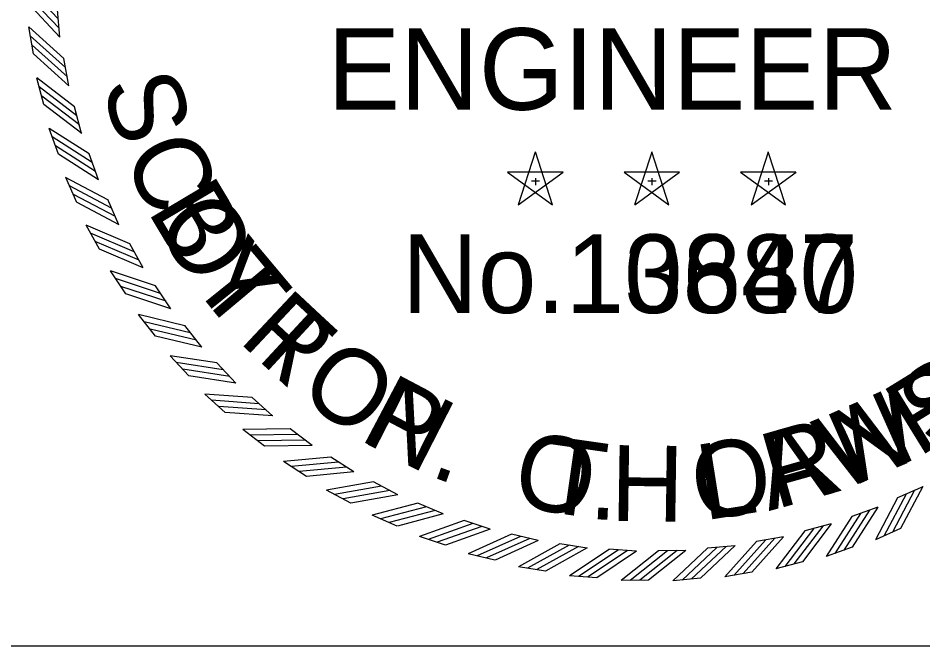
# Model space of a CAD drawing. Extents: x 0 to 1228740, y 0 to 152440.
# Drawn here: x 30.801 to 32.593, y 17.405 to 18.649 of the extents above; entities that cross this region are included whole.
import ezdxf

# ---------------------------------------------------------------- set-up
doc = ezdxf.new("R2010")
doc.units = 0
for name, color, linetype in [('R_No Plot', 7, 'Continuous'), ('STAMP_BOL', 7, 'Continuous'), ('STAMP_PP', 7, 'Continuous')]:
    doc.layers.add(name, color=color, linetype=linetype)

msp = doc.modelspace()

# ---------------------------------------------------------------- linework, layer by layer
at = {"layer": 'R_No Plot'}
msp.add_lwpolyline([(30.6665, 20.1432), (30.6665, 17.4052), (33.4231, 17.4052)], dxfattribs=at)
at = {"layer": 'STAMP_BOL'}
for p, q in [((30.8837, 18.6117), (30.8787, 18.666)), ((30.8314, 18.5785), (30.822, 18.6321)), ((30.9013, 18.5154), (30.8918, 18.5691)), ((30.8519, 18.478), (30.8381, 18.5306)), ((30.9268, 18.4209), (30.9129, 18.4737)), ((30.8807, 18.3796), (30.8626, 18.4309)), ((30.96, 18.3289), (30.9419, 18.3803)), ((31.8255, 18.384), (31.7915, 18.2795)), ((31.8594, 18.2796), (31.8256, 18.3841)), ((32.0563, 18.384), (32.0222, 18.2795)), ((32.0902, 18.2796), (32.0564, 18.3841)), ((32.2871, 18.384), (32.253, 18.2795)), ((32.321, 18.2796), (32.2871, 18.3841)), ((31.8804, 18.3441), (31.7705, 18.3442)), ((31.7706, 18.3441), (31.8594, 18.2795)), ((31.7916, 18.2796), (31.8805, 18.3441)), ((32.1112, 18.3441), (32.0013, 18.3442)), ((32.0014, 18.3441), (32.0902, 18.2795)), ((32.0224, 18.2796), (32.1113, 18.3441)), ((32.3419, 18.3441), (32.2321, 18.3442)), ((32.2322, 18.3441), (32.321, 18.2795)), ((32.2532, 18.2796), (32.3421, 18.3441)), ((30.9175, 18.2838), (30.8952, 18.3335)), ((31.8177, 18.3266), (31.834, 18.3266)), ((31.8256, 18.3324), (31.8256, 18.3186)), ((32.0485, 18.3266), (32.0648, 18.3266)), ((32.0564, 18.3324), (32.0564, 18.3186)), ((32.2793, 18.3266), (32.2956, 18.3266)), ((32.2872, 18.3324), (32.2872, 18.3186)), ((31.0007, 18.2399), (30.9784, 18.2896)), ((30.9621, 18.1915), (30.9357, 18.2391)), ((31.0487, 18.1545), (31.0223, 18.2022)), ((31.0141, 18.1031), (30.9839, 18.1484)), ((31.1035, 18.0734), (31.0732, 18.1188)), ((31.0733, 18.0193), (31.0395, 18.062)), ((31.1648, 17.9971), (31.1309, 18.0399)), ((31.1392, 17.9407), (31.1019, 17.9804)), ((31.2322, 17.9262), (31.1949, 17.966)), ((31.2113, 17.8678), (31.1709, 17.9043)), ((31.3052, 17.861), (31.2648, 17.8976)), ((31.2892, 17.8012), (31.246, 17.8342)), ((31.3834, 17.8021), (31.34, 17.8352)), ((31.3724, 17.7411), (31.3266, 17.7705)), ((31.4661, 17.7499), (31.4202, 17.7793)), ((31.5529, 17.7046), (31.5047, 17.7301)), ((31.4602, 17.6882), (31.4121, 17.7136)), ((32.593, 17.7208), (32.5433, 17.6985)), ((31.6432, 17.6667), (31.593, 17.6882)), ((32.504, 17.6801), (32.4526, 17.662)), ((31.5521, 17.6427), (31.5021, 17.6641)), ((31.7362, 17.6364), (31.6845, 17.6536)), ((32.4119, 17.6469), (32.3592, 17.633)), ((31.6475, 17.6049), (31.5959, 17.6221)), ((31.8315, 17.6138), (31.7785, 17.6267)), ((32.3175, 17.6214), (32.2637, 17.6119)), ((32.549, 17.6376), (32.4994, 17.6153)), ((31.9283, 17.5992), (31.8744, 17.6077)), ((32.2212, 17.6038), (32.1669, 17.5988)), ((31.7456, 17.5751), (31.6928, 17.588)), ((32.0259, 17.5927), (31.9715, 17.5967)), ((32.1238, 17.5942), (32.0692, 17.5937)), ((32.4533, 17.6008), (32.402, 17.5827)), ((32.3549, 17.572), (32.3023, 17.5582)), ((31.8459, 17.5536), (31.7922, 17.5621)), ((32.2544, 17.5515), (32.2008, 17.5421)), ((31.9476, 17.5404), (31.8934, 17.5444)), ((32.0501, 17.5356), (31.9957, 17.5351)), ((32.1526, 17.5393), (32.0984, 17.5343))]:
    msp.add_line(p, q, dxfattribs=at)
for points in [[(30.8802, 18.6479), (30.8157, 18.7165)], [(30.8823, 18.6291), (30.8178, 18.6977)], [(30.8838, 18.6117), (30.8193, 18.6803)], [(30.8918, 18.5691), (30.8219, 18.6321)], [(30.8948, 18.5512), (30.8249, 18.6142)], [(30.8985, 18.5327), (30.8286, 18.5957)], [(30.9014, 18.5154), (30.8315, 18.5784)], [(30.9129, 18.4736), (30.838, 18.5307)], [(30.9174, 18.456), (30.8425, 18.5131)], [(30.9226, 18.4379), (30.8477, 18.4949)], [(30.9269, 18.4209), (30.852, 18.478)], [(30.9418, 18.3802), (30.8625, 18.4309)], [(30.9477, 18.3631), (30.8684, 18.4138)], [(30.9544, 18.3454), (30.8751, 18.3961)], [(30.9601, 18.3288), (30.8808, 18.3795)], [(30.9784, 18.2895), (30.8951, 18.3335)], [(30.9857, 18.2729), (30.9024, 18.3169)], [(30.9938, 18.2559), (30.9105, 18.2998)], [(31.0008, 18.2398), (30.9176, 18.2838)], [(31.0223, 18.2022), (30.9357, 18.2391)], [(31.0309, 18.1862), (30.9443, 18.2232)], [(31.0404, 18.1699), (30.9538, 18.2068)], [(31.0487, 18.1545), (30.9621, 18.1914)], [(31.0732, 18.1187), (30.9839, 18.1484)], [(31.0831, 18.1036), (30.9938, 18.1332)], [(31.094, 18.0881), (31.0046, 18.1177)], [(31.1035, 18.0734), (31.0142, 18.1031)], [(31.1309, 18.0398), (31.0394, 18.062)], [(31.142, 18.0255), (31.0505, 18.0477)], [(31.1541, 18.0109), (31.0626, 18.0331)], [(31.1649, 17.9971), (31.0734, 18.0193)], [(31.1949, 17.9659), (31.1019, 17.9804)], [(31.2072, 17.9526), (31.1142, 17.9671)], [(31.2204, 17.939), (31.1274, 17.9536)], [(31.2323, 17.9262), (31.1393, 17.9407)], [(31.2648, 17.8975), (31.1709, 17.9043)], [(31.2781, 17.8852), (31.1842, 17.8921)], [(31.2924, 17.8729), (31.1985, 17.8797)], [(31.3053, 17.861), (31.2114, 17.8678)], [(31.3401, 17.8351), (31.2459, 17.8342)], [(31.3544, 17.824), (31.2602, 17.8231)], [(31.3696, 17.8129), (31.2755, 17.8119)], [(31.3835, 17.8021), (31.2893, 17.8012)], [(31.4203, 17.7792), (31.3265, 17.7705)], [(31.4354, 17.7693), (31.3417, 17.7606)], [(31.4516, 17.7595), (31.3578, 17.7507)], [(31.4662, 17.7499), (31.3725, 17.7411)], [(31.5048, 17.7301), (31.4121, 17.7136)], [(31.5207, 17.7215), (31.428, 17.705)], [(31.5376, 17.713), (31.4449, 17.6965)], [(32.577, 17.7139), (32.5331, 17.6306)], [(32.5931, 17.7209), (32.5491, 17.6377)], [(31.553, 17.7046), (31.4603, 17.6882)], [(32.5434, 17.6985), (32.4994, 17.6152)], [(32.56, 17.7058), (32.516, 17.6225)], [(31.5931, 17.6881), (31.5021, 17.6641)], [(31.6097, 17.6808), (31.5187, 17.6568)], [(32.5041, 17.6802), (32.4534, 17.6009)], [(31.6272, 17.6738), (31.5362, 17.6497)], [(31.6433, 17.6667), (31.5522, 17.6427)], [(32.4527, 17.6619), (32.402, 17.5826)], [(32.4698, 17.6678), (32.4191, 17.5885)], [(32.4875, 17.6745), (32.4368, 17.5952)], [(31.6845, 17.6536), (31.5958, 17.6221)], [(31.7017, 17.6477), (31.613, 17.6162)], [(31.7197, 17.6421), (31.631, 17.6106)], [(32.395, 17.6427), (32.338, 17.5678)], [(32.412, 17.647), (32.3549, 17.5721)], [(31.7363, 17.6364), (31.6476, 17.6049)], [(31.7785, 17.6267), (31.6927, 17.588)], [(31.7961, 17.6222), (31.7103, 17.5835)], [(32.3175, 17.6215), (32.2545, 17.5516)], [(32.3593, 17.633), (32.3022, 17.5581)], [(32.3768, 17.6375), (32.3198, 17.5626)], [(31.8146, 17.6182), (31.7288, 17.5795)], [(31.8315, 17.6139), (31.7457, 17.5752)], [(31.8744, 17.6077), (31.7921, 17.562)], [(31.8923, 17.6047), (31.81, 17.559)], [(32.2212, 17.6039), (32.1526, 17.5394)], [(32.2638, 17.6119), (32.2008, 17.542)], [(32.2817, 17.6149), (32.2186, 17.545)], [(32.3002, 17.6186), (32.2372, 17.5487)], [(31.9111, 17.6022), (31.8287, 17.5565)], [(31.9283, 17.5993), (31.846, 17.5536)], [(31.9716, 17.5966), (31.8933, 17.5443)], [(31.9896, 17.5951), (31.9114, 17.5428)], [(32.0085, 17.5942), (31.9302, 17.5419)], [(32.026, 17.5927), (31.9477, 17.5404)], [(32.0693, 17.5937), (31.9956, 17.5351)], [(32.0874, 17.5937), (32.0137, 17.5351)], [(32.1063, 17.5943), (32.0326, 17.5357)], [(32.1238, 17.5943), (32.0501, 17.5357)], [(32.1669, 17.5988), (32.0983, 17.5343)], [(32.185, 17.6003), (32.1164, 17.5358)], [(32.2038, 17.6024), (32.1352, 17.538)]]:
    msp.add_lwpolyline(points, dxfattribs=at)
at = {"layer": 'STAMP_PP'}
for p, q in [((30.8837, 18.6117), (30.8787, 18.666)), ((30.8314, 18.5785), (30.822, 18.6321)), ((30.9013, 18.5154), (30.8918, 18.5691)), ((30.8519, 18.478), (30.8381, 18.5306)), ((30.9268, 18.4209), (30.9129, 18.4737)), ((30.8807, 18.3796), (30.8626, 18.4309)), ((30.96, 18.3289), (30.9419, 18.3803)), ((31.8255, 18.384), (31.7915, 18.2795)), ((31.8594, 18.2796), (31.8256, 18.3841)), ((32.0563, 18.384), (32.0222, 18.2795)), ((32.0902, 18.2796), (32.0564, 18.3841)), ((32.2871, 18.384), (32.253, 18.2795)), ((32.321, 18.2796), (32.2871, 18.3841)), ((31.8804, 18.3441), (31.7705, 18.3442)), ((31.7706, 18.3441), (31.8594, 18.2795)), ((31.7916, 18.2796), (31.8805, 18.3441)), ((32.1112, 18.3441), (32.0013, 18.3442)), ((32.0014, 18.3441), (32.0902, 18.2795)), ((32.0224, 18.2796), (32.1113, 18.3441)), ((32.3419, 18.3441), (32.2321, 18.3442)), ((32.2322, 18.3441), (32.321, 18.2795)), ((32.2532, 18.2796), (32.3421, 18.3441)), ((30.9175, 18.2838), (30.8952, 18.3335)), ((31.8177, 18.3266), (31.834, 18.3266)), ((31.8256, 18.3324), (31.8256, 18.3186)), ((32.0485, 18.3266), (32.0648, 18.3266)), ((32.0564, 18.3324), (32.0564, 18.3186)), ((32.2793, 18.3266), (32.2956, 18.3266)), ((32.2872, 18.3324), (32.2872, 18.3186)), ((31.0007, 18.2399), (30.9784, 18.2896)), ((30.9621, 18.1915), (30.9357, 18.2391)), ((31.0487, 18.1545), (31.0223, 18.2022)), ((31.0141, 18.1031), (30.9839, 18.1484)), ((31.1035, 18.0734), (31.0732, 18.1188)), ((31.0733, 18.0193), (31.0395, 18.062)), ((31.1648, 17.9971), (31.1309, 18.0399)), ((31.1392, 17.9407), (31.1019, 17.9804)), ((31.2322, 17.9262), (31.1949, 17.966)), ((31.2113, 17.8678), (31.1709, 17.9043)), ((31.3052, 17.861), (31.2648, 17.8976)), ((31.2892, 17.8012), (31.246, 17.8342)), ((31.3834, 17.8021), (31.34, 17.8352)), ((31.3724, 17.7411), (31.3266, 17.7705)), ((31.4661, 17.7499), (31.4202, 17.7793)), ((31.5529, 17.7046), (31.5047, 17.7301)), ((31.4602, 17.6882), (31.4121, 17.7136)), ((32.593, 17.7208), (32.5433, 17.6985)), ((31.6432, 17.6667), (31.593, 17.6882)), ((32.504, 17.6801), (32.4526, 17.662)), ((31.5521, 17.6427), (31.5021, 17.6641)), ((31.7362, 17.6364), (31.6845, 17.6536)), ((32.4119, 17.6469), (32.3592, 17.633)), ((31.6475, 17.6049), (31.5959, 17.6221)), ((31.8315, 17.6138), (31.7785, 17.6267)), ((32.3175, 17.6214), (32.2637, 17.6119)), ((32.549, 17.6376), (32.4994, 17.6153)), ((31.9283, 17.5992), (31.8744, 17.6077)), ((32.2212, 17.6038), (32.1669, 17.5988)), ((31.7456, 17.5751), (31.6928, 17.588)), ((32.0259, 17.5927), (31.9715, 17.5967)), ((32.1238, 17.5942), (32.0692, 17.5937)), ((32.4533, 17.6008), (32.402, 17.5827)), ((32.3549, 17.572), (32.3023, 17.5582)), ((31.8459, 17.5536), (31.7922, 17.5621)), ((32.2544, 17.5515), (32.2008, 17.5421)), ((31.9476, 17.5404), (31.8934, 17.5444)), ((32.0501, 17.5356), (31.9957, 17.5351)), ((32.1526, 17.5393), (32.0984, 17.5343))]:
    msp.add_line(p, q, dxfattribs=at)
for points in [[(30.8802, 18.6479), (30.8157, 18.7165)], [(30.8823, 18.6291), (30.8178, 18.6977)], [(30.8838, 18.6117), (30.8193, 18.6803)], [(30.8918, 18.5691), (30.8219, 18.6321)], [(30.8948, 18.5512), (30.8249, 18.6142)], [(30.8985, 18.5327), (30.8286, 18.5957)], [(30.9014, 18.5154), (30.8315, 18.5784)], [(30.9129, 18.4736), (30.838, 18.5307)], [(30.9174, 18.456), (30.8425, 18.5131)], [(30.9226, 18.4379), (30.8477, 18.4949)], [(30.9269, 18.4209), (30.852, 18.478)], [(30.9418, 18.3802), (30.8625, 18.4309)], [(30.9477, 18.3631), (30.8684, 18.4138)], [(30.9544, 18.3454), (30.8751, 18.3961)], [(30.9601, 18.3288), (30.8808, 18.3795)], [(30.9784, 18.2895), (30.8951, 18.3335)], [(30.9857, 18.2729), (30.9024, 18.3169)], [(30.9938, 18.2559), (30.9105, 18.2998)], [(31.0008, 18.2398), (30.9176, 18.2838)], [(31.0223, 18.2022), (30.9357, 18.2391)], [(31.0309, 18.1862), (30.9443, 18.2232)], [(31.0404, 18.1699), (30.9538, 18.2068)], [(31.0487, 18.1545), (30.9621, 18.1914)], [(31.0732, 18.1187), (30.9839, 18.1484)], [(31.0831, 18.1036), (30.9938, 18.1332)], [(31.094, 18.0881), (31.0046, 18.1177)], [(31.1035, 18.0734), (31.0142, 18.1031)], [(31.1309, 18.0398), (31.0394, 18.062)], [(31.142, 18.0255), (31.0505, 18.0477)], [(31.1541, 18.0109), (31.0626, 18.0331)], [(31.1649, 17.9971), (31.0734, 18.0193)], [(31.1949, 17.9659), (31.1019, 17.9804)], [(31.2072, 17.9526), (31.1142, 17.9671)], [(31.2204, 17.939), (31.1274, 17.9536)], [(31.2323, 17.9262), (31.1393, 17.9407)], [(31.2648, 17.8975), (31.1709, 17.9043)], [(31.2781, 17.8852), (31.1842, 17.8921)], [(31.2924, 17.8729), (31.1985, 17.8797)], [(31.3053, 17.861), (31.2114, 17.8678)], [(31.3401, 17.8351), (31.2459, 17.8342)], [(31.3544, 17.824), (31.2602, 17.8231)], [(31.3696, 17.8129), (31.2755, 17.8119)], [(31.3835, 17.8021), (31.2893, 17.8012)], [(31.4203, 17.7792), (31.3265, 17.7705)], [(31.4354, 17.7693), (31.3417, 17.7606)], [(31.4516, 17.7595), (31.3578, 17.7507)], [(31.4662, 17.7499), (31.3725, 17.7411)], [(31.5048, 17.7301), (31.4121, 17.7136)], [(31.5207, 17.7215), (31.428, 17.705)], [(31.5376, 17.713), (31.4449, 17.6965)], [(32.577, 17.7139), (32.5331, 17.6306)], [(32.5931, 17.7209), (32.5491, 17.6377)], [(31.553, 17.7046), (31.4603, 17.6882)], [(32.5434, 17.6985), (32.4994, 17.6152)], [(32.56, 17.7058), (32.516, 17.6225)], [(31.5931, 17.6881), (31.5021, 17.6641)], [(31.6097, 17.6808), (31.5187, 17.6568)], [(32.5041, 17.6802), (32.4534, 17.6009)], [(31.6272, 17.6738), (31.5362, 17.6497)], [(31.6433, 17.6667), (31.5522, 17.6427)], [(32.4527, 17.6619), (32.402, 17.5826)], [(32.4698, 17.6678), (32.4191, 17.5885)], [(32.4875, 17.6745), (32.4368, 17.5952)], [(31.6845, 17.6536), (31.5958, 17.6221)], [(31.7017, 17.6477), (31.613, 17.6162)], [(31.7197, 17.6421), (31.631, 17.6106)], [(32.395, 17.6427), (32.338, 17.5678)], [(32.412, 17.647), (32.3549, 17.5721)], [(31.7363, 17.6364), (31.6476, 17.6049)], [(31.7785, 17.6267), (31.6927, 17.588)], [(31.7961, 17.6222), (31.7103, 17.5835)], [(32.3175, 17.6215), (32.2545, 17.5516)], [(32.3593, 17.633), (32.3022, 17.5581)], [(32.3768, 17.6375), (32.3198, 17.5626)], [(31.8146, 17.6182), (31.7288, 17.5795)], [(31.8315, 17.6139), (31.7457, 17.5752)], [(31.8744, 17.6077), (31.7921, 17.562)], [(31.8923, 17.6047), (31.81, 17.559)], [(32.2212, 17.6039), (32.1526, 17.5394)], [(32.2638, 17.6119), (32.2008, 17.542)], [(32.2817, 17.6149), (32.2186, 17.545)], [(32.3002, 17.6186), (32.2372, 17.5487)], [(31.9111, 17.6022), (31.8287, 17.5565)], [(31.9283, 17.5993), (31.846, 17.5536)], [(31.9716, 17.5966), (31.8933, 17.5443)], [(31.9896, 17.5951), (31.9114, 17.5428)], [(32.0085, 17.5942), (31.9302, 17.5419)], [(32.026, 17.5927), (31.9477, 17.5404)], [(32.0693, 17.5937), (31.9956, 17.5351)], [(32.0874, 17.5937), (32.0137, 17.5351)], [(32.1063, 17.5943), (32.0326, 17.5357)], [(32.1238, 17.5943), (32.0501, 17.5357)], [(32.1669, 17.5988), (32.0983, 17.5343)], [(32.185, 17.6003), (32.1164, 17.5358)], [(32.2038, 17.6024), (32.1352, 17.538)]]:
    msp.add_lwpolyline(points, dxfattribs=at)

# ---------------------------------------------------------------- texts
at = {"layer": 'STAMP_BOL'}
for s, height, rotation, p in [('ENGINEER', 0.16155, 360, (31.4137, 18.4677)), ('B', 0.1503, 300.7985, (31.0556, 18.2683)), ('Y', 0.1503, 308.8241, (31.1364, 18.1328)), ('No.13640', 0.15578, 360, (31.5614, 18.0649)), ('R', 0.1503, 316.8497, (31.2353, 18.0099)), ('O', 0.1503, 324.8753, (31.3504, 17.9021)), ('R', 0.1503, 31.6338, (32.5843, 17.7778)), ('N', 0.1503, 332.9009, (31.4794, 17.8113)), ('W', 0.1503, 22.8786, (32.4262, 17.7098)), ('A', 0.1503, 15.5826, (32.2878, 17.6722)), ('O', 0.1503, 349.3169, (31.7759, 17.6861)), ('L', 0.1503, 9.0162, (32.1601, 17.6536)), ('.', 0.1503, 357.3425, (31.9309, 17.6569))]:
    msp.add_text(s, height=height, rotation=rotation, dxfattribs=at).set_placement(p)
at = {"layer": 'STAMP_PP'}
for s, height, p in [('ENGINEER', 0.16155, (31.4137, 18.4677)), ('No.10887', 0.15578, (31.5614, 18.0649))]:
    msp.add_text(s, height=height, dxfattribs=at).set_placement(p)
for s, rotation, p in [('S', 286.9475, (30.9653, 18.5171)), ('C', 294.2435, (31.0071, 18.3799)), ('O', 301.9044, (31.0694, 18.2429)), ('T', 309.93, (31.1536, 18.1096)), ('T', 317.226, (31.2456, 17.9997)), ('S', 32.7397, (32.6095, 17.7919)), ('P', 332.1828, (31.4737, 17.8153)), ('N', 23.9845, (32.4533, 17.72)), ('R', 15.9589, (32.302, 17.6757)), ('T', 351.882, (31.832, 17.6734)), ('H', 359.178, (31.974, 17.6531)), ('O', 7.9332, (32.146, 17.6529)), ('.', 340.2084, (31.6136, 17.7427))]:
    msp.add_text(s, height=0.1503, rotation=rotation, dxfattribs=at).set_placement(p)

doc.saveas('drawing.dxf')
